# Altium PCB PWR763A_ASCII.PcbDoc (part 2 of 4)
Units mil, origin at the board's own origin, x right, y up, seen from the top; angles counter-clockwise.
Board outline 5000 x 7000 mil, 4 copper layers (Top Layer, Signal Layer 1, Signal Layer 2, Bottom Layer), stack 61.2 mil thick; 559 components, 281 nets, 1477 pads, 685 vias.
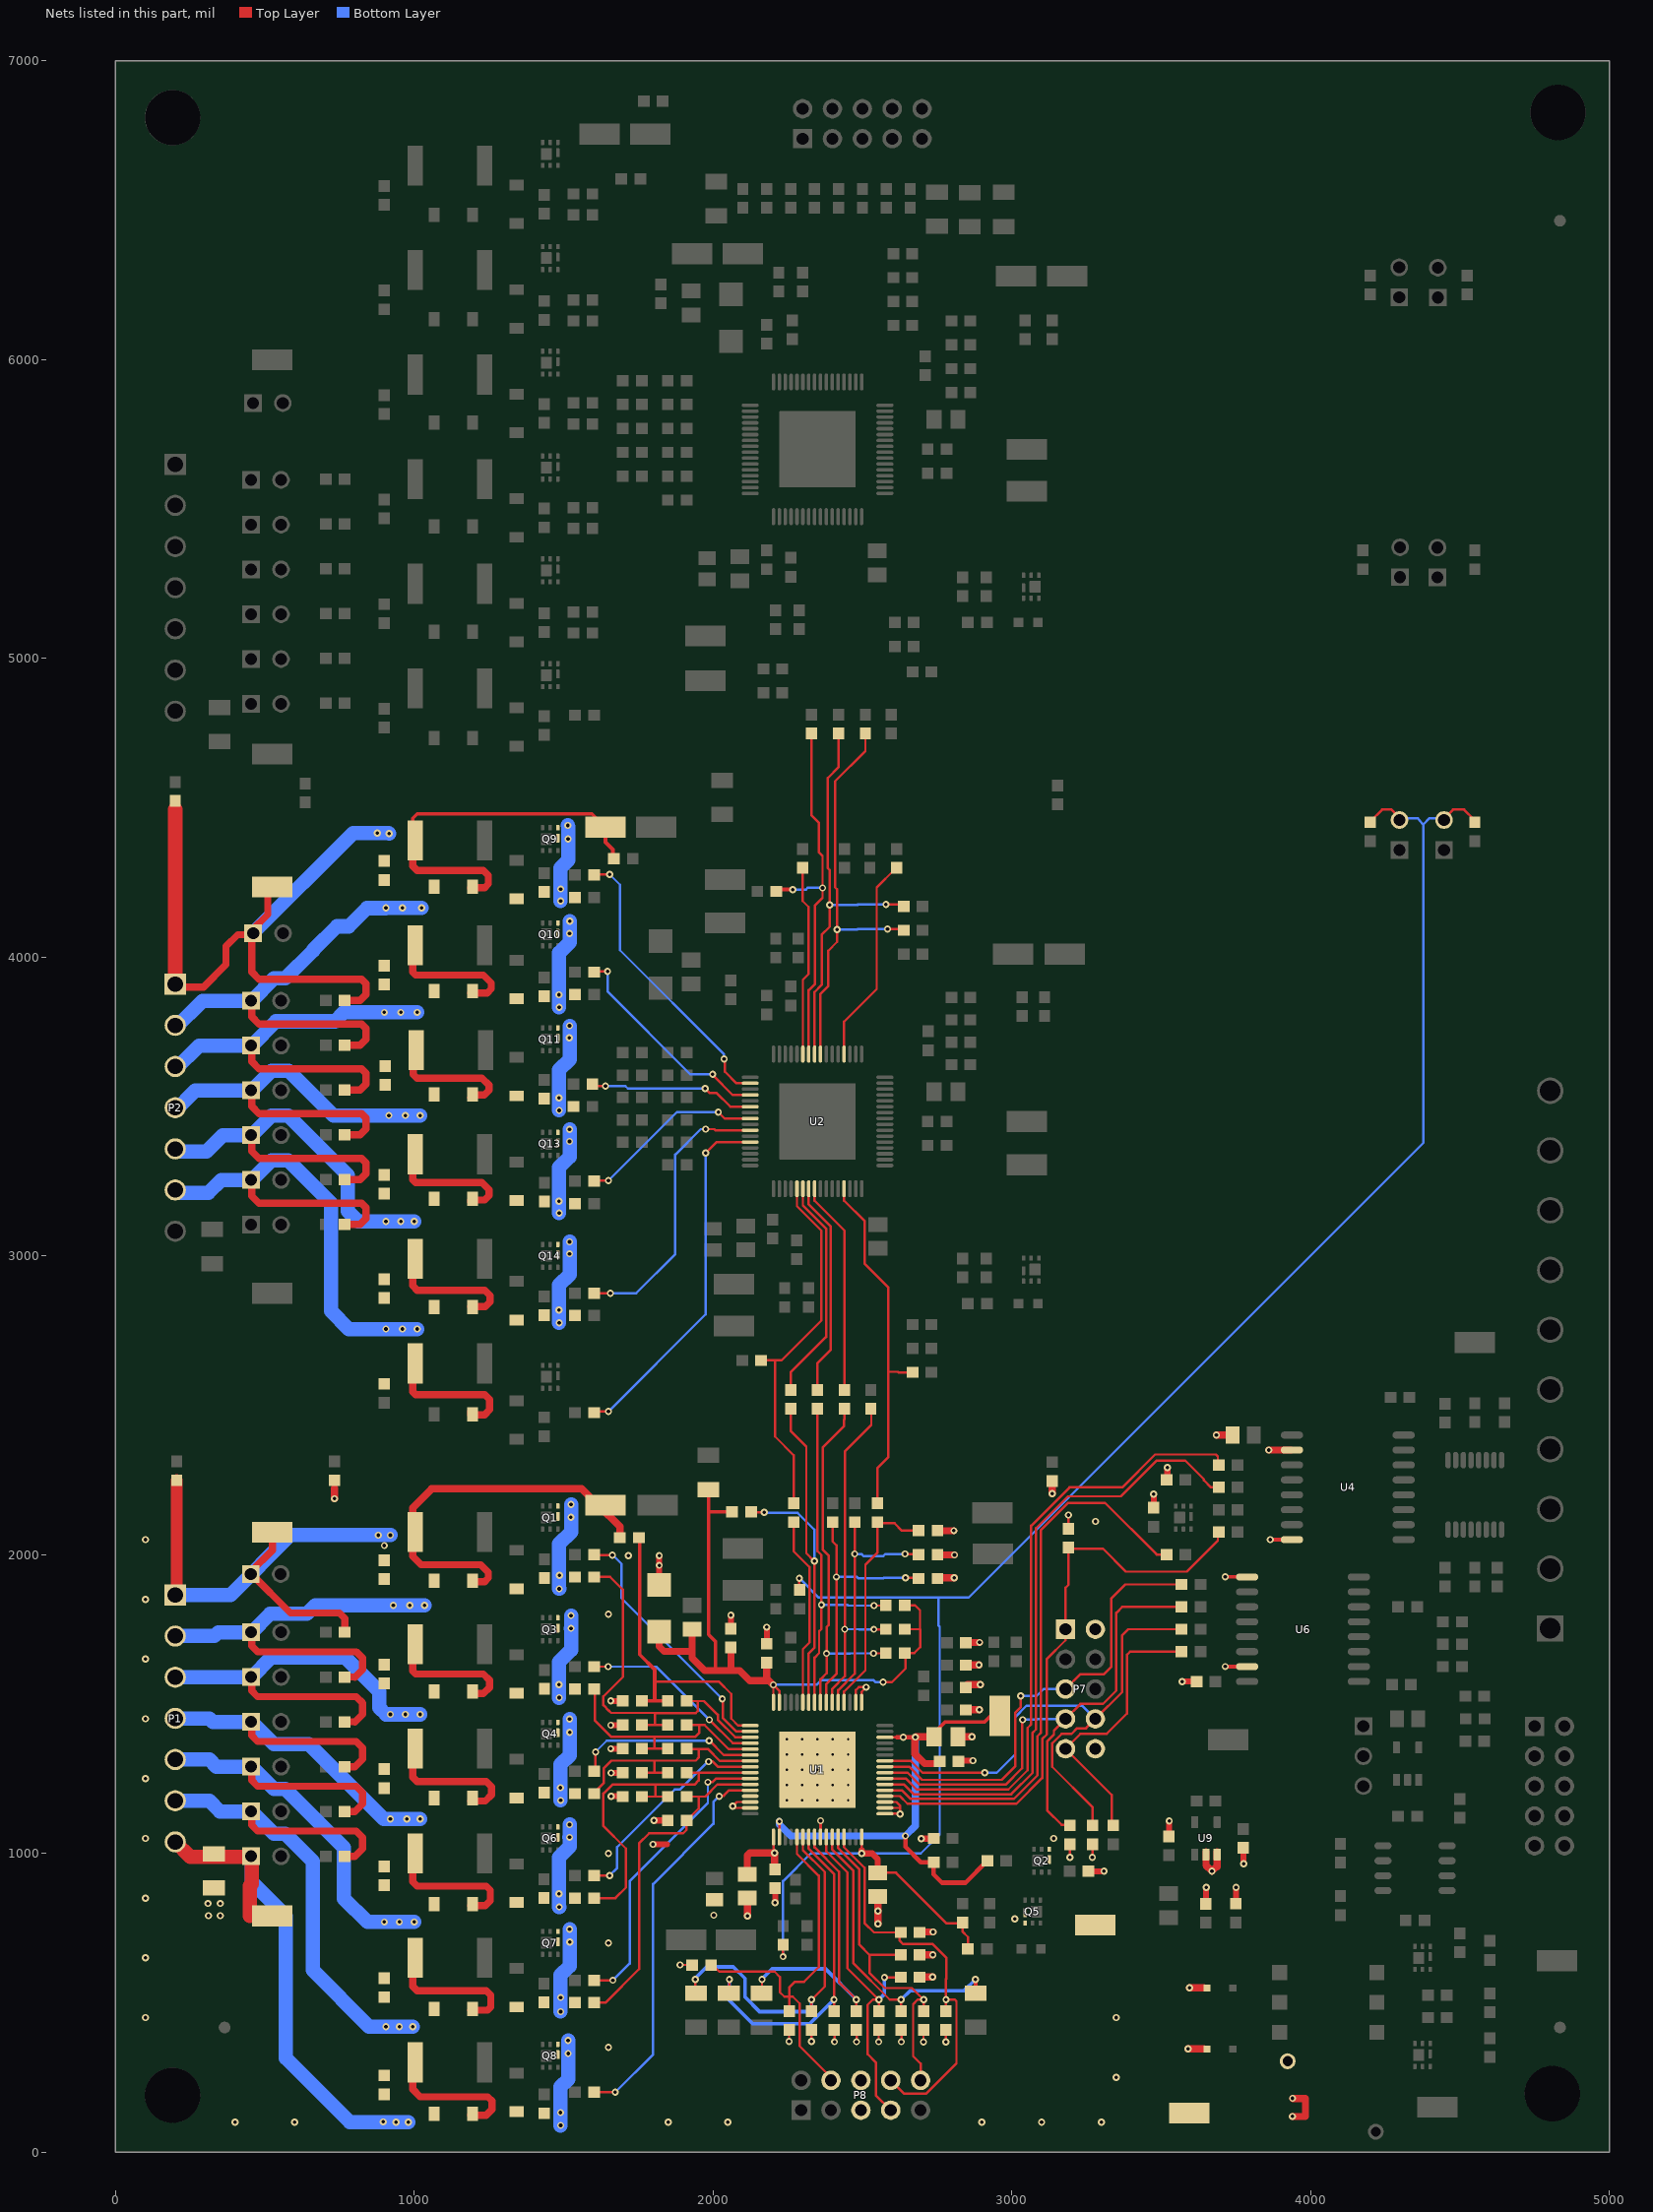
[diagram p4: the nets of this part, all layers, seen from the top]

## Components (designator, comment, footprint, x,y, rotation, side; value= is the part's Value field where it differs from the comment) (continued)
Z5 "MMSZ5232B-7-F" SOD-123 1343,1600 r270 top
Z6 "MMSZ5232B-7-F" SOD-123 1131,1185 r180 top
Z7 "MMSZ5232B-7-F" SOD-123 1343,1250 r270 top
Z8 "MMSZ5232B-7-F" SOD-123 1131,830 r180 top
Z9 "MMSZ5232B-7-F" SOD-123 1343,900 r270 top
Z10 "MMSZ5232B-7-F" SOD-123 1131,479 r180 top
Z11 "MMSZ5232B-7-F" SOD-123 1343,550 r270 top
Z12 "MMSZ5232B-7-F" SOD-123 1131,128 r180 top
Z13 "MMSZ5232B-7-F" SOD-123 1343,200 r270 top
Z14 "MMSZ5232B-7-F" SOD-123 1131,4236 r180 top
Z15 "SMAJ36CA" SMA 1825,3975 r270 top
Z16 "MMSZ5232B-7-F" SOD-123 1343,4260 r270 top
Z17 "MMSZ5232B-7-F" SOD-123 1131,3887 r180 top
Z18 "MMSZ5232B-7-F" SOD-123 1343,3925 r270 top
Z19 "MMSZ5232B-7-F" SOD-123 1131,3540 r180 top
Z20 "MMSZ5232B-7-F" SOD-123 1343,3600 r270 top
Z21 "MMSZ5232B-7-F" SOD-123 1131,3191 r180 top
Z22 "MMSZ5232B-7-F" SOD-123 1343,3250 r270 top
Z23 "MMSZ5232B-7-F" SOD-123 1131,2828 r180 top
Z24 "MMSZ5232B-7-F" SOD-123 1343,2850 r270 top
Z25 "MMSZ5232B-7-F" SOD-123 1131,2470 r180 top
Z26 "MMSZ5232B-7-F" SOD-123 1343,2450 r270 top
Z27 "SMAJ36CA" SMA 2060,6140 r270 top
Z28 "MMSZ5232B-7-F" SOD-123 1131,6485 r180 top
Z29 "MMSZ5232B-7-F" SOD-123 1343,6520 r270 top
Z30 "MMSZ5232B-7-F" SOD-123 1131,6135 r180 top
Z31 "MMSZ5232B-7-F" SOD-123 1343,6170 r270 top
Z32 "MMSZ5232B-7-F" SOD-123 1131,5790 r180 top
Z33 "MMSZ5232B-7-F" SOD-123 1343,5820 r270 top
Z34 "MMSZ5232B-7-F" SOD-123 1131,5442 r180 top
Z35 "MMSZ5232B-7-F" SOD-123 1343,5470 r270 top
Z36 "MMSZ5232B-7-F" SOD-123 1131,5089 r180 top
Z37 "MMSZ5232B-7-F" SOD-123 1343,5120 r270 top
Z38 "MMSZ5232B-7-F" SOD-123 1131,4734 r180 top
Z39 "MMSZ5232B-7-F" SOD-123 1343,4770 r270 top
ZZ1 "This Assembly Note is for PCB labels only" AssemblyNoteLabel 150,7739 r0 top
ZZ2 "These assemblies are ESD sensitive, ESD precautions shall be observed." AssemblyNote 150,7630.11 r0 top
ZZ3 "These assemblies must be clean and free from flux and all contaminants. Use of no clean flux is not acceptable." AssemblyNote 150,7541.56 r0 top
ZZ4 "These assemblies must comply with workmanship standards IPC-A-610 Class 2, unless otherwise specified." AssemblyNote 150,7453 r0 top
ZZ5 "Please place P9- Terminal; P10- Terminal; P11- Terminal; to P1; P2; P3" AssemblyNote 145,7320 r0 top

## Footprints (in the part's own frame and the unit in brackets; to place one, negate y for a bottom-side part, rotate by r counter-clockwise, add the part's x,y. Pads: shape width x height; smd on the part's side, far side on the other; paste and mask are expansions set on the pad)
0603#1 [mm] "0603 from SM-752 data"
  rect 1x0.95 smd: 1(-0.8,0) 2(0.8,0)
  silkscreen extent -1.52,-0.69 1.52,0.69
0603#2 [mm] "0603 from SM-752 data"
  rect 1x0.95 smd: 1(-2.832,4.877) 2(-1.232,4.877)
  silkscreen extent -3.56,4.19 -0.51,5.57
0805_145 [mm] "0805 / 1.45mm height"
  rect 1.15x1.45 smd: 1(-0.9,0) 2(0.9,0)
  silkscreen extent -0.1,-0.8 0.1,0.8
0805_HV [mil] "0805 with 30mil clearance between pads"
  rect 50x63 smd: 1(-40,0) 2(40,0)
  silkscreen extent -74,-40 74,40
1206 [mm] "1206 from SM-752 data"
  rect 1.3x1.85 smd: 1(-1.45,0) 2(1.45,0)
  silkscreen extent -2.4,-1.21 2.4,1.21
2512 [mm] "Chip Resistor, Body 6.3x3.2mm, IPC Medium Density"
  rect 1.3x3.4 smd: 1(-2.95,0) 2(2.95,0)
  silkscreen extent -1.9,-1.6 1.9,1.6
APT1608_Yellow [mm] "SMD, 2-Leads, Body 0.8x1.6mm"
  rect 0.8x0.8 smd: 1(-0.825,0) 2(0.825,0)
  silkscreen extent -1,-0.7 1.8,0.7
AssemblyNote [mil] "Assembly Note"
AssemblyNoteLabel [mil] "Assembly Note for PCB Labels"
CAPRD750W60D700H1000 [mm] "muRata"
  round 1.35 hole 0.85: 1(-3.75,3) 2(3.75,-3)
  silkscreen extent -3.5,-2.95 3.47,3.05
Coilcraft_Q4470-CL [mm] "SMD, 6-Leads, Body 6.6x6.99mm, Pitch 2.54mm"
  rect 1.27x1.27 smd: 1(-4.13,2.54) 2(-4.13,0) 3(-4.13,-2.54) 4(4.13,-2.54) 5(4.13,0) 6(4.13,2.54)
  silkscreen extent -3.4,-3.5 3.3,3.8
CONN_5103308-1 [mm] "TE Connectivity (AMP) Rev E datasheet"
  rect 1.65x1.65 hole 1.016 mask+0: 1(-5.08,-1.27)
  round 1.65 hole 1.016 mask+0: 2(-5.08,1.27) 3(-2.54,-1.27) 4(-2.54,1.27) 5(0,-1.27) 6(0,1.27) 7(2.54,-1.27) 8(2.54,1.27) 9(5.08,-1.27) 10(5.08,1.27)
  silkscreen extent -10.16,-4.57 10.16,4.57
CONN_PEC02SAAN [mm] "SULLINS"
  rect 1.5x1.5 hole 1.016: 1(-1.27,0)
  round 1.5 hole 1.016: 2(1.27,0)
  silkscreen extent -3.45,-1.27 2.54,1.27
CONN_PEC03SAAN [mm] "SULLINS"
  rect 1.5x1.5 hole 1.016: 1(-2.54,0)
  round 1.5 hole 1.016: 2(0,0) 3(2.54,0)
  silkscreen extent -4.72,-1.27 3.81,1.27
D0008A_N [mm] "SOIC, 8-Leads, Body 4.9x3.9mm, Pitch 1.27mm, IPC Medium Density"
  oval 1.45x0.6 smd: 1(-2.725,1.905) 2(-2.725,0.635) 3(-2.725,-0.635) 4(-2.725,-1.905) 5(2.725,-1.905) 6(2.725,-0.635) 7(2.725,0.635) 8(2.725,1.905)
  silkscreen extent -3.3,-2.5 0.9,2.5
DBV0005A_N [mm] "SOT23, 5-Leads, Body 2.9x1.6mm, Pitch 0.95mm, Lead Span 2.8mm, IPC Medium Density"
  rrect17% 1x0.6 smd: 1(-1.375,0.95) 2(-1.375,0) 3(-1.375,-0.95) 4(1.375,-0.95) 5(1.375,0.95)
  silkscreen extent -1.63,-1.55 0.38,1.55
DW0016A_N [mm] "SOIC, 16-Leads, Body 10.3x7.5mm, Pitch 1.27mm, IPC Medium Density"
  oval 1.9x0.6 smd: 1(-4.75,4.445) 2(-4.75,3.175) 3(-4.75,1.905) 4(-4.75,0.635) 5(-4.75,-0.635) 6(-4.75,-1.905) 7(-4.75,-3.175) 8(-4.75,-4.445) 9(4.75,-4.445) 10(4.75,-3.175) 11(4.75,-1.905) 12(4.75,-0.635) 13(4.75,0.635) 14(4.75,1.905) 15(4.75,3.175) 16(4.75,4.445)
  silkscreen extent -5.6,-5.25 3,5.25
FCC_disclaimer [mil]
Fiducial10-20#1 [mm]
  round 1 smd mask+0.5: 1(0,0)
  Top Layer keep-out circle w1.178: c0,0 r0.5
Fiducial10-20#2 [mm]
  round 1 smd mask+0.5: 1(0,-0.076)
  Top Layer keep-out circle w1.178: c0,0 r0.5
Fiducial10-20#3 [mm]
  round 1 smd mask+0.5: 1(0.102,0)
  Top Layer keep-out circle w1.178: c0,0 r0.5
IEC_HighVoltage_Small [mil]
  silkscreen extent -107,-88 107,97
Keystone_9030 [mm] "BRD SPT SNAP LOCK SCREW MNT 3/8\""
  round 4.7 hole 4.7 unplated mask+0: ""(0,0)
  silkscreen extent -3.3,-3.3 3.3,3.3
Label_650x200 [mil] "Thermal Transfer Label"
  round 1 on Mech13: 0(0,0)
  silkscreen extent -325,-100 325,100
Molex_395021007 [mm] "Header(Shrouded), 3.5mm, 7x1,  R/A, TH"
  rect 1.8x1.8 hole 1.3: 1(-10.5,0)
  round 1.8 hole 1.3: 2(-7,0) 3(-3.5,0) 4(0,0) 5(3.5,0) 6(7,0) 7(10.5,0)
  silkscreen extent -12.95,-7.87 12.95,1.52
PAP0064F_N [mm] "Thin QFP, 64-Leads, Body 10x10mm, Pitch 0.5mm, Thermal Pad 6.5x6.5mm, IPC Medium Density"
  rrect100% 1.45x0.3 smd: 1(-5.725,3.75) 2(-5.725,3.25) 3(-5.725,2.75) 4(-5.725,2.25) 5(-5.725,1.75) 6(-5.725,1.25) 7(-5.725,0.75) 8(-5.725,0.25) 9(-5.725,-0.25) 10(-5.725,-0.75) 11(-5.725,-1.25) 12(-5.725,-1.75) 13(-5.725,-2.25) 14(-5.725,-2.75) 15(-5.725,-3.25) 16(-5.725,-3.75) 33(5.725,-3.75) 34(5.725,-3.25) 35(5.725,-2.75) 36(5.725,-2.25) 37(5.725,-1.75) 38(5.725,-1.25) 39(5.725,-0.75) 40(5.725,-0.25) 41(5.725,0.25) 42(5.725,0.75) 43(5.725,1.25) 44(5.725,1.75) 45(5.725,2.25) 46(5.725,2.75) 47(5.725,3.25) 48(5.725,3.75)
  rrect100% 0.3x1.45 smd: 17(-3.75,-5.725) 18(-3.25,-5.725) 19(-2.75,-5.725) 20(-2.25,-5.725) 21(-1.75,-5.725) 22(-1.25,-5.725) 23(-0.75,-5.725) 24(-0.25,-5.725) 25(0.25,-5.725) 26(0.75,-5.725) 27(1.25,-5.725) 28(1.75,-5.725) 29(2.25,-5.725) 30(2.75,-5.725) 31(3.25,-5.725) 32(3.75,-5.725) 49(3.75,5.725) 50(3.25,5.725) 51(2.75,5.725) 52(2.25,5.725) 53(1.75,5.725) 54(1.25,5.725) 55(0.75,5.725) 56(0.25,5.725) 57(-0.25,5.725) 58(-0.75,5.725) 59(-1.25,5.725) 60(-1.75,5.725) 61(-2.25,5.725) 62(-2.75,5.725) 63(-3.25,5.725) 64(-3.75,5.725)
  rrect2% 6.5x6.5 smd: 65(0,0)
  silkscreen extent -5.67,-4.25 4.25,4.57
Pb-Free_Overlay_Small [mil]
  silkscreen extent -46,-46 46,46
PW0016A_N [mm] "TSOP, 16-Leads, Body 5x4.4mm, Pitch 0.65mm, IPC Medium Density"
  oval 1.4x0.45 smd: 1(-2.95,2.275) 2(-2.95,1.625) 3(-2.95,0.975) 4(-2.95,0.325) 5(-2.95,-0.325) 6(-2.95,-0.975) 7(-2.95,-1.625) 8(-2.95,-2.275) 9(2.95,-2.275) 10(2.95,-1.625) 11(2.95,-0.975) 12(2.95,-0.325) 13(2.95,0.325) 14(2.95,0.975) 15(2.95,1.625) 16(2.95,2.275)
  silkscreen extent -3.5,-2.55 1.85,2.75
Samtec_HPM-10-05-T-S [mm] "Header, 5.08mm, 10x1, TH"
  rect 2.25x2.25 hole 1.75: 1(-22.86,0)
  round 2.25 hole 1.75: 2(-17.78,0) 3(-12.7,0) 4(-7.62,0) 5(-2.54,0) 6(2.54,0) 7(7.62,0) 8(12.7,0) 9(17.78,0) 10(22.86,0)
  silkscreen extent -25.47,-3.17 25.33,3.8
SMA [mm] "Molded Diode, 2-Leads, Body 4.3x2.6mm, IPC Medium Density, based on OnSemi component dimensions and land pattern"
  rect 2x2 smd: 1(-2,0) 2(2,0)
  silkscreen extent -3.66,-1.57 2.79,1.57
SNT-100-BK-G [mil] "Samtec STEP model"
  round 1 on Mech3: 0(0,0)
SOD-123 [mm] "On Semi recommended land pattern"
  rect 0.915x1.22 smd: 1(-1.637,0) 2(1.637,0)
  silkscreen extent -2.74,-1.17 2.03,1.17
sod-323 [mm] "NXP recommended land pattern"
  rect 0.6x0.6 smd paste-0.05: 1(-1.1,0) 2(1.1,0)
  silkscreen extent -1.8,-0.77 1.53,0.77
Testpoint_Keystone_Miniature [mil] "Miniature SMT test point"
  rect 135x70 smd: 1(0,0)
  silkscreen extent -78,-46 78,45
TI_Stacked_Overlay_Small [mil]
TRANS_NexFET_Q2 [mm] "TI recommended land pattern M0167-01"
  rrect33% 0.45x0.3 smd: 1(-0.975,0.65) 2(-0.975,0) 3(-0.975,-0.65) 4(0.975,-0.65) 5(0.975,0) 6(0.975,0.65)
  rrect33% 0.75x0.3 smd paste-0.025: 7(0.095,-0.65)
  rrect11% 1x0.95 smd paste-0.025: 8(0,0.325)
  silkscreen extent -1.15,-1.15 1.15,1.15

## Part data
C1 C2 C3 C4 C5 C10 C11 C12 C13 C14 C17 C18 C20 C21 C25 C26 C28 C29 C40 C41 C42 C44 C46 C48 C51 C52 C54 C55 C57 C60 C66 C67 C78 C79 C80 C82 C84 C86 C89 C90 C92 C93 C95 C98 C100 C101 C107 C113 C114 C116 C118 C120 C121 C122 C123 C124 C125 C129 C132 C133: "CAP, CERM, 0.1 µF, 50 V, +/- 10%, X7R, 0603"
C6 C7 C8 C9: "CAP, CERM, 3300 pF, 50 V, +/- 10%, X7R, 0603"
C15 C16 C19 C24 C27 C30 C34 C49 C50 C53 C56 C61 C68 C69 C87 C88 C91 C94 C99 C102 C103: "CAP, CERM, 0.1 µF, 100 V, +/- 10%, X7R, 0603"
C22 C23 C58 C59 C96 C97: "CAP, CERM, 0.047 µF, 16 V, +/- 10%, X7R, 0603"
C31 C32 C33 C70 C71 C72 C104 C105 C106: "CAP, CERM, 0.1 µF, 16 V, +/- 10%, X7R, 0603"
C35 C36 C37 C38 C62 C63 C64 C65 C73 C74 C75 C76 C108 C109 C110 C111: "CAP, CERM, 33 pF, 50 V, +/- 5%, C0G/NP0, 0603"
C39 C77 C112 C126 C135: "CAP, CERM, 10 µF, 10 V, +/- 20%, X7R, 0805"
C43 C45 C47 C81 C83 C85 C115 C117 C119: "CAP, CERM, 2.2 µF, 10 V, +/- 10%, X7R, 0805"
C127: "CAP, CERM, 1 µF, 16 V, +/- 10%, X7R, 0603"
C128 C130 C131 C134: "CAP, CERM, 4.7 µF, 10 V, +/- 10%, X5R, 0603"
C136: "CAP, CERM, 150 pF, 50 V, +/- 5%, C0G/NP0, 0603"
C137: "CAP, CERM, 1000 pF, 3150 V, +80/-20%, E, Radial Disc D7x6mm"
"CAUTION 1": library part IEC_HighVoltage, "IEC 61010-1 High Voltage Warning"
D1 D2 D3: "LED, Yellow, SMD"
D4: "MOSFET, P-CH, -20 V, -20 A, SON 2x2mm"
D5 D6: "Diode, Schottky, 30 V, 0.2 A, SOD-323"
FID1 FID2 FID3: "Fiducial mark.  There is nothing to buy or mount."
H1 H2 H3 H4: "BRD SPT SNAP LOCK SCREW MNT 3/8\""
J1 J2 J3 J4 J5 J6 J7 J8 J9 JP1 JP2 JP3 JP4 JP5 JP6 JP7 JP8 JP9 JP10 JP11 JP12 JP13 JP14 JP15 JP16 JP17 JP18: "Header, 100mil, 2x1, Tin, TH"
JP19: "Header, 100mil, 3x1, Tin, TH"
L1: "Inductor, Wirewound, Ferrite, 10uH, 0.12A, 0.5 ohm, SMD"
LBL1: library part THT-14-423-10, "Thermal Transfer Printable Labels, 0.650\" W x 0.200\" H - 10,000 per roll"
Logo1: library part TI_Logo, "Texas Instrument Corporate Signature"
Logo2: library part Pb-Free
Logo3: library part FCC_disclaimer, "FCC_disclaimer"
P1 P2 P3: "Header(Shrouded), 3.5mm, 7x1,  R/A, TH"
P4 P5 P7 P8: "Header (shrouded), 100mil, 5x2, Gold, TH"
P6: "Header, 5.08mm, 10x1, Tin, TH"
Q1 Q2 Q3 Q4 Q5 Q6 Q7 Q8 Q9 Q10 Q11 Q12 Q13 Q14 Q15 Q16 Q17 Q18 Q19 Q20 Q21 Q22 Q23 Q24: "MOSFET, N-CH, 25 V, 5 A, SON 2x2mm"
R1 R10 R11 R12 R54 R55 R56 R65: "RES, 1.00 k, 1%, 0.25 W, 1206"
R2 R3 R4 R5 R6 R7 R8 R9 R20 R37 R57 R58 R59 R60 R61 R62 R63 R64 R94 R96 R99 R101 R103 R104 R105 R106 R108 R140 R141 R144 R146 R177 R179 R181 R184 R185 R198 R199 R200: "RES, 0, 5%, 0.1 W, 0603"
R13 R14 R15 R16 R17 R18 R30 R31 R32 R33 R34 R35 R47 R48 R49 R50 R51 R52: "RES, 1.0 k, 5%, 0.1 W, 0603"
R19 R29 R36 R46 R53: "RES, 0, 5%, 0.25 W, 1206"
R21 R22 R23 R24 R25 R26 R27 R28 R38 R39 R40 R41 R42 R43 R44 R45 R67 R69 R72 R73 R76 R79 R87 R92 R95 R98 R102 R109 R111 R114 R116 R118 R120 R122 R125 R131 R136 R138 R142 R145 R148 R151 R153 R155 R157 R159 R162 R164 R173 R175 R178 R182 R186 R202 R214: "RES, 1.00 k, 0.1%, 0.1 W, 0603"
R66 R74 R81 R93 R100 R110 R113 R119 R124 R133 R139 R147 R150 R156 R160 R167 R176 R183: "RES, 47, 5%, 1 W, 2512"
R68 R115 R152: "RES, 0, 5%, 0.125 W, 0805"
R70 R75 R80 R82 R83 R196 R207 R208 R209 R211: "RES, 10.0 k, 1%, 0.1 W, 0603"
R71 R78 R90 R97 R107 R112 R117 R121 R129 R137 R143 R149 R154 R158 R163 R174 R180 R187 R190 R191 R192 R195: "RES, 1.0 M, 5%, 0.1 W, 0603"
R77 R123 R161: "RES, 1.6 k, 5%, 0.1 W, 0603"
R84 R85 R127 R128 R165 R166: "RES, 1.47 k, 1%, 0.1 W, 0603"
R86 R126 R135 R168 R172 R204: "RES, 100 k, 1%, 0.1 W, 0603"
R88 R130 R171 R188 R189 R193 R194 R197 R201 R203 R205 R206: "RES, 100, 5%, 0.1 W, 0603"
R89 R91 R132 R134 R169 R170: "RES, 1.82 k, 1%, 0.1 W, 0603"
R210: "RES, 2.00, 1%, 0.1 W, 0603"
R212: "RES, 523 k, 1%, 0.1 W, 0603"
R213: "RES, 169 k, 1%, 0.1 W, 0603"
R215: "RES, 1.0, 5%, 0.1 W, 0603"
RT1 RT2 RT3 RT4 RT5 RT6: "Thermistor NTC, 10.0k ohm, 1%, 0603"
SH-J1 SH-J2 SH-J3 SH-J4 SH-J5 SH-J6 SH-J7 SH-J8 SH-JP1 SH-JP2 SH-JP3 SH-JP4 SH-JP5 SH-JP6 SH-JP7 SH-JP8 SH-JP9 SH-JP10 SH-JP11 SH-JP12 SH-JP13 SH-JP14 SH-JP15 SH-JP16 SH-JP17 SH-JP18 SH-JP19: "Shunt, 100mil, Gold plated, Black"
T1: "Transformer, 400 uH, SMT"
TP1 TP2 TP3 TP4 TP5 TP6 TP-1 TP-2 TP-3 TP-4 TP-5 TP-6 TP-7 TP-8 TP-9 TP-10 TP-11 TP-12 TP-13 TP-14 TP-15 TP-16 TP-17 TP-18 TP-19 TP-AGN TP-C1 TP-C2 TP-C3 TP-C4 TP-C5 TP-C6 TP-SW1 TP-VPROG1 TP-VPROG2 TP-VPROG3 TP-VSS1 TP-VSS2 TP-VSS3 TPTP-VSS1: "Test Point, Miniature, SMT"
TP-20: "LOW PROFILE, TH"
U1 U2 U3: "Lithium-Ion Battery Monitor and Secondary Protection IC for Electric and Hybrid, -40 to 85 degC, 64-pin HTQFP (PAP), Green (RoHS & no Sb/Br)"
U4 U6: "25 Mbps Quad Channels, 3 / 1, Digital Isolator, 3.3 V / 5 V, -40 to +125 degC, 16-pin SOIC (DW), Green (RoHS & no Sb/Br)"
U5: "Remote 8-Bit I2C and SMBus Low-Power I/O Expander with Reset and Configuration Registers, 2.3 to 5.5 V, -40 to 85 degC, 16-pin TSSOP (PW), Green (RoHS & no Sb/Br)"
U7: "Single Output LDO, 100 mA, Fixed 3.3 V Output, 2.7 to 10 V Input, with Low IQ, 5-pin SOT-23 (DBV), -40 to 125 degC, Green (RoHS & no Sb/Br)"
U8: "LOW POWER CURRENT MODE PUSH-PULL PWM, D0008A"
U9: "Ultralow-Power 100-mA Low-Dropout Linear Regulators, DBV0005A"
Z1 Z15 Z27: "Diode, TVS, Bi, 36 V, 400 W, SMA"
Z2 Z3 Z4 Z5 Z6 Z7 Z8 Z9 Z10 Z11 Z12 Z13 Z14 Z16 Z17 Z18 Z19 Z20 Z21 Z22 Z23 Z24 Z25 Z26 Z28 Z29 Z30 Z31 Z32 Z33 Z34 Z35 Z36 Z37 Z38 Z39: "Diode, Zener, 5.6 V, 500 mW, SOD-123"
ZZ1: library part AssemblyNoteLabel
ZZ2 ZZ3 ZZ4 ZZ5: library part AssemblyNote

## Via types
v1: diameter 24, hole 12, Top Layer to Bottom Layer, tented both sides, 607 vias
v2: diameter 19.68, hole 7.87, Top Layer to Bottom Layer, 75 vias
v3: diameter 22, hole 10, Top Layer to Bottom Layer, tented both sides, 3 vias

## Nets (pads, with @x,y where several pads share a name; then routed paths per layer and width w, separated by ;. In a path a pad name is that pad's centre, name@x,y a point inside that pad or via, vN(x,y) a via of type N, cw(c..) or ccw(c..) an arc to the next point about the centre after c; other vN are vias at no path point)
1-ALERT: R189.1 U1.38 | length 2099.8
  Top Layer w8: U1.38@2578.35,1230.79 2638.9,1230.79 2671.68,1198 2998,1198 3069.97,1269.97 3069.97,1403.6 3081.1,1414.73 3081.1,2088.02 3188.08,2195 3365,2195 3485,2315 3580.36,2315 3642.76,2252.6 3642.76,2249.24 3667,2225 R189.1@3690,2225
1-ALERT_N: C37.1 R39.1 U1.57 | length 1205.3
  Top Layer w8: U1.57@2340.16,1508.35 2340.16,1655.08 2355.13,1670.05 2355.13,1743.04 2363.13,1751.04 v1(2363.13,1832.04) 2363.13,1998.23 2350,2011.36 R39.1@2350,2485 ; v1(2538.91,1829.32) 2575,1829.32 C37.1@2575,1830
  Bottom Layer w8: v1(2363.13,1832.04) 2449.66,1832.04 2452.38,1829.32 v1(2538.91,1829.32)
1-ALERT_S: R55.2 R59.2 U1.23 | length 1144.9
  Top Layer w8: R55.2@2053,531.57 2055,533.57 v1(2055,578) ; U1.23@2320.47,1051.65 2320.47,1015.22 2405,930.69 v1(2405,510) R59.2@2405,475
  Bottom Layer w12: v1(2055,578) 2055,507 2132,430 2325,430 v1(2405,510)
1-CB1: R111.1 U1.12 | length 1316.4
  Top Layer w8: R111.1@1601.5,200 1601.72,200.22 v1(1672.75,200.22) ; v1@2022,1193 2036,1193 2054.1,1211.1 U1.12@2124.61,1211.1
  Bottom Layer w8: v1(1672.75,200.22) 1799.55,327.01 1799.55,897.05 2001.53,1099.03 2001.53,1171.96 v1@2020.61,1191.04
  other v1: 2020.96,1190.97
1-CB2: R102.1 U1.10 | length 1009
  Top Layer w8: R102.1@1601.5,575 v1@1664.93,575 ; v1@1979,1238 1998,1238 2010.47,1250.47 U1.10@2124.61,1250.47
  Bottom Layer w8: v1@1664.9,575 1721,631.1 1721,906.02 1982.96,1167.98 v1(1982.96,1237.97)
  other v1: 1664.96,574.97
1-CB3: R95.1 U1.8 | length 725
  Top Layer w8: R95.1@1601.5,925 1602.33,925.83 v1(1654.07,925.83) ; v1@1987,1308 1998,1308 2016.16,1289.84 U1.8@2124.61,1289.84
  Bottom Layer w8: v1(1654.07,925.83) 1679.49,951.25 1679.49,1020.91 1871.81,1213.24 1889.08,1213.24 v1@1982.46,1306.62
  other v1: 1984.96,1306.97
1-CB4: R87.1 U1.6 | length 618.8
  Top Layer w8: R87.1@1601.5,1275 1606.96,1280.46 v1(1606.96,1338.97) ; v1@1988,1377.31 2036.1,1329.21 U1.6@2124.61,1329.21
  Bottom Layer w8: v1@1606.55,1339.16 1644.36,1376.97 v1(1986.96,1376.97)
1-CB5: R76.1 U1.4 | length 628.8
  Top Layer w8: R76.1@1601.5,1625 v1@1648.93,1625 ; v1(1987.96,1446.97) 2066.42,1368.58 U1.4@2124.61,1368.58
  Bottom Layer w8: v1@1649.41,1624.83 1810.1,1624.83 v1(1987.96,1446.97)
  other v1: 1648.96,1624.97
1-CB6: R69.1 U1.2 | length 868.8
  Top Layer w8: R69.1@1601.5,2000 1603.53,1997.97 v1(1662.96,1997.97) ; v1@2032.65,1515.22 2032.65,1453.35 2078.05,1407.95 U1.2@2124.61,1407.95
  Bottom Layer w8: v1@1663.97,1998.87 1693.86,1968.98 1693.86,1854.07 v1(2030.96,1516.97)
1-CELL1: C34.2 C42.1 JP17.1 P1.6 Q7.4 Q7.7 R52.2 R107.1 R109.2 R110.2 Z10.2 Z11.2 Z12.1 | length 2632.2
  Top Layer w24: JP17.1@456,1140 456,1094 475.34,1074.66 805.63,1074.66 826.99,1053.3 826.99,1014.97 801.51,989.49 801,990 R52.2@770,990 ; R110.2@995,300 995,210 1020,185 1246.45,185 1259.94,171.51 1259.94,142.51 1240.14,122.71 1189.5,122.71 Z12.1@1189.5,125
  Bottom Layer w48: P1.6@200,1176.02 313.89,1176.02 349.91,1140 456,1140 531,1065 568.68,1065 660,973.68 660,608.43 848.43,420 v1(905,420) v1(950,420) v1(995,420) ; v1(1490,470) 1490,593 1520,623 1520,702.84 v1(1520.82,702.84) 1520,706 v1(1520,746)
  other v1: 1490.24,517.34
1-CELL2: C28.2 C34.1 JP16.1 P1.5 Q6.4 Q6.7 R51.2 R97.1 R98.2 R100.2 Z8.2 Z9.2 Z10.1 | length 2434.2
  Top Layer w24: JP16.1@456,1290 456,1244 475.34,1224.66 805.63,1224.66 826.99,1203.3 826.99,1164.97 801.51,1139.49 801,1140 R51.2@770,1140 ; R100.2@995,650 995,555 1010,540 1241.45,540 1256.21,525.24 1256.21,485.78 1245.43,475 Z10.1@1189.5,475
  Bottom Layer w48: P1.5@200,1313.81 313.89,1313.82 337.71,1290 456,1290 531,1215 568.68,1215 765,1018.68 765,848.43 843.43,770 v1(900,770) v1(950,770) v1(1000,770) ; v1(1485.15,820.54) 1485,824 1485,987 1520,1022 1520,1053.48 v1(1519.89,1053.48) 1520,1056 v1(1520,1096)
  other v1: 1484,864
1-CELL3: C25.2 C28.1 JP15.1 P1.4 Q4.4 Q4.7 R50.2 R90.1 R92.2 R93.2 Z6.2 Z7.2 Z8.1 | length 2257.2
  Top Layer w24: JP15.1@456,1440 456,1394 475.34,1374.66 805.63,1374.66 826.99,1353.3 826.99,1314.97 801.51,1289.49 801,1290 R50.2@770,1290 ; R93.2@995,1000 995,905 1010,890 1241.45,890 1254.55,876.9 1254.55,841.55 1238,825 Z8.1@1189.5,825
  Bottom Layer w48: P1.4@200,1451.61 313.89,1451.61 325.5,1440 456,1440 531,1365 647.44,1365 897.44,1115 v1(920,1115) v1(975,1115) v1(1020,1115) ; v1(1490,1177) 1490,1298 1520,1328 v1(1520,1449)
  other v1: 1489.5,1219.45 1520.15,1405.14
1-CELL4: C20.2 C25.1 JP14.1 P1.3 Q3.4 Q3.7 R49.2 R78.1 R79.2 R81.2 Z4.2 Z5.2 Z6.1 | length 2266.3
  Top Layer w24: JP14.1@456,1590 456,1544 475.34,1524.66 805.63,1524.66 826.99,1503.3 826.99,1464.97 801.51,1439.49 801,1440 R49.2@770,1440 ; R81.2@995,1350 995,1255 1010,1240 1241.45,1240 1258.28,1223.17 1258.28,1195.28 1238,1175 Z6.1@1189.5,1175
  Bottom Layer w48: P1.3@200,1589.41 331.6,1589.41 332.19,1590 456,1590 521,1655 770,1655 883,1542 883,1487.19 905.19,1465 v1(920,1465) v1(970,1465) v1(1020,1465) ; v1(1485,1521) 1485,1641 1525,1681 1525,1753.17 v1(1524.74,1753.17) 1525,1756 v1(1525,1796)
  other v1: 1484.41,1564.58
1-CELL5: C17.2 C20.1 JP13.1 P1.2 Q1.4 Q1.7 R48.2 R71.1 R72.2 R74.2 Z2.2 Z3.2 Z4.1 | length 2161.2
  Top Layer w24: JP13.1@456,1740 456,1694 475.34,1674.66 805.63,1674.66 826.99,1653.3 826.99,1614.97 801.51,1589.49 801,1590 R48.2@770,1590 ; R74.2@995,1700 995,1610 1005,1600 1231.45,1600 1251.65,1579.8 1251.65,1555.16 1231.35,1534.86 Z4.1@1199.36,1534.86
  Bottom Layer w48: P1.2@200,1727.2 331.6,1727.2 344.4,1740 456,1740 518,1802 640.34,1802 668.34,1830 v1(930,1830) v1(985,1830) v1(1035,1830) ; v1(1485.26,1885.34) 1485,1890 1485,2036 1525,2076 v1(1525,2168)
  other v1: 1486,1931 1524.45,2124.9
1-CELL6: C17.1 J1.1 P1.1 R37.1 R47.2 R66.2 R67.2 TP5.1 TP-C1.1 Z2.1 | length 3101.4
  Top Layer w24: J1.1@453,1935 453,1943 525,2015 TP5.1@525,2075 ; J1.1@455,1935 585.48,1804.52 750,1804.52 768.09,1786.43 768.09,1740 R47.2@770,1740 ; R66.2@995,2075 995,1994 1022.75,1966.25 1222.57,1966.25 1248.03,1940.78 1248.03,1921.31 1236.02,1909.3 Z2.1@1198.8,1909.3
  Top Layer w25: R66.2@995,2075 995,2156.5 1058.5,2220 1560,2220 1615,2165 1617,2165 1688.52,2093.48 R67.2@1688.52,2056.75
  Top Layer w40: P1.1@200,1865 205,1870 R37.1@205,2248.5
  Bottom Layer w48: P1.1@200,1865 385,1865 585,2065 v1(880,2065) v1(920,2065)
  other v1: 900,2030
1-CONV: P7.1 R83.1 R194.1 U1.36 | length 1977.4
  Top Layer w8: U1.36@2578.35,1191.42 2625.37,1191.42 2650.79,1166 3016,1166 3101.97,1251.97 3101.97,1382.55 3117.77,1398.35 3117.77,1650.7 3180,1712.93 P7.1@3180,1750 3180,1888.75 3190,1898.75 3190,2020 3305,2020 3382.18,1942.82 3585.82,1942.82 3690,2047 R194.1@3690,2075
1-CONV_N: R42.1 U1.59 | length 627.8
  Top Layer w8: R42.1@2270,2105 2270,2011.16 2323,1958.16 2323,1705.62 2300.79,1683.41 U1.59@2300.79,1508.35
1-CONV_S: C10.1 P8.4 R57.2 U1.21 | length 1345.7
  Top Layer w8: C10.1@1993.5,626 1999,626 2021,604 2206,604 2224,586 2224,535 2239,520 2255,520 ; R57.2@2255,475 2255,520 ; U1.21@2281.1,1051.65 2281.1,997.99 2354,925.1 2354,619 2305,570 2275,570 2255,550 2255,520 ; P8.4@2395,240 2395,250 2290,355 2290,497 2267,520 2255,520
1-CS_N: R45.1 R105.2 U1.52 | length 788.2
  Top Layer w8: U1.52@2438.58,1508.35 2438.58,1541 2510.12,1612.54 2510.12,1966.02 2550,2005.91 2550,2105 2607.5,2105 2632.5,2080 R105.2@2685,2080
1-CS_S: C13.1 P8.8 R64.2 U1.29 | length 1353.1
  Top Layer w8: U1.29@2438.58,1051.65 2438.58,1020.36 2507,951.94 2507,767 2539,735 2625,735 2625,707 2636.31,695.69 2735.74,695.69 2780.58,650.85 2780.58,580 2780,579.42 v1(2780,510) ; P8.8@2595,240 2640,195 2712.93,195 2815,297.07 2815,505 2810,510 v1(2780,510) ; R64.2@2780,475 v1(2780,510)
1-DRDY: R196.1 U1.37 | length 1905.2
  Top Layer w8: U1.37@2578.35,1211.1 2632.42,1211.1 2661.53,1182 3007,1182 3085.97,1260.97 3085.97,1391.82 3097.1,1402.95 3097.1,2081.43 3189.02,2173.35 3311.66,2173.35 3485.01,2000 R196.1@3515,2000
1-DRDY_N: C38.1 R38.1 U1.58 | length 1357.3
  Top Layer w8: C38.1@2130.67,2142.55 2130.67,2141.06 v1(2171.82,2141.06) ; R38.1@2260,2485 2260,2413.7 2312.5,2361.21 2312.5,2004.66 v1(2339.13,1978.02) 2339.13,1687.91 2320.47,1669.24 U1.58@2320.47,1508.35
  Bottom Layer w8: v1(2171.82,2141.06) 2171.82,2139.7 2283,2139.7 2339.13,2083.57 v1(2339.13,1978.02)
1-DRDY_S: R54.2 R58.2 U1.22 | length 1208.7
  Top Layer w8: v1(1941,578) 1941,534.57 R54.2@1943,532.57 ; U1.22@2300.79,1051.65 2300.79,1010.44 2374,937.23 2374,554 v1(2330,510) R58.2@2330,475
  Bottom Layer w12: v1(1941,578) 1941,582 1979,620 2068,620 2107,581 2107,519 2156,470 2313,470 2330,487 v1(2330,510)
1-FAULT: R188.1 U1.39 | length 2094.3
  Top Layer w8: U1.39@2578.35,1250.47 2644.95,1250.47 2681.42,1214 2989,1214 3053.2,1278.2 3053.2,1419.71 3065.1,1431.61 3065.1,2096.38 3193.72,2225 3370,2225 3480,2335 3683,2335 3690,2328 R188.1@3690,2300
1-FAULT_N: C36.1 R40.1 U1.56 | length 1221.4
  Top Layer w8: U1.56@2359.84,1508.35 2359.84,1582.4 2380.13,1602.68 v1(2380.13,1669.05) 2380.13,1757.04 2387.13,1764.04 2387.13,1996.86 2368,2015.99 2368,2359.86 2439.12,2430.98 2439.12,2452.05 2440,2452.93 R40.1@2440,2485 ; v1(2537.09,1669.32) 2575,1669.32 C36.1@2575,1670
  Bottom Layer w8: v1(2380.13,1669.05) 2458.48,1669.05 2458.75,1669.32 v1(2537.09,1669.32)
1-FAULT_S: R56.2 R60.2 U1.24 | length 1055.2
  Top Layer w8: R56.2@2163,531.57 2164,532.57 v1(2164,578) ; U1.24@2340.16,1051.65 2340.16,1020 2421.61,938.55 2421.61,568.39 v1(2480,510) R60.2@2480,475
  Bottom Layer w12: v1(2164,578) 2164,579 2198,613 2377,613 v1(2480,510)
1-LDOA: C44.1 C45.1 U1.17 | length 259.3
  Top Layer w8: v1@2202.36,1001.21 U1.17@2202.36,1051.65
  Top Layer w24: C45.1@2115,930 2115,992.77 2123.44,1001.21 2202.36,1001.21 v1(2205.7,1001.21) 2205.7,950 C44.1@2205,950
1-LDOD1: C46.1 C47.1 R70.2 R94.2 TP-VPROG1.1 U1.18 U1.46 | length 1845.4
  Top Layer w8: v1(2222,1107) v1(2222,1107) U1.18@2222.05,1054.61 ; U1.46@2575.39,1388.27 2616.11,1388.27
  Top Layer w12: C47.1@2740,1390 2740,1402.23 2777.77,1440 2910,1440 TP-VPROG1.1@2960,1490
  Top Layer w15: v1(2643.85,1058.21) 2643.85,1021.75 2695.6,970 R94.2@2738.5,970 2738.5,929.58 2766.62,901.46 2844.96,901.46 R70.2@2918.5,975
  Top Layer w16: 2616.11,1388.27 2636.56,1388.27 v1(2637,1388) 2636.56,1388.32 2636.56,1388.46 v1@2670.48,1388.46 ; v1@2676,1384.02 2671.02,1389 v1(2677,1389)
  Top Layer w24: v1@2676,1384.02 2676,1332.22 2708.22,1300 C46.1@2755,1300 ; v1(2677,1389) 2678,1390 C47.1@2740,1390
  Bottom Layer w24: v1(2222,1107) 2222,1097.03 2260.82,1058.21 v1(2643.85,1058.21) 2677,1091.36 v1(2677,1389)
1-REG50: C22.1 C23.1 C43.1 J2.2 J3.2 R77.2 R86.2 RT1.2 RT2.2 U1.32 | length 6598.8
  Top Layer w8: v1(2234.61,654.07) 2234.61,693.11 C22.1@2235,693.5 ; v1(2289,1921) 2289,1884.5 2291,1882.5 C23.1@2290,1881.5 ; U1.32@2497.64,1054.61 2497.77,1054.47 v1@2497.77,1009.77 ; C43.1@2551,935 2612.5,935 2782.5,765 R86.2@2835,765 ; R86.2@2835,768.5 R86.2@2835,765 ; R77.2@2853.5,680 2853.5,719.5 2835,738 R86.2@2835,765 ; RT2.2@4200,4440 4200,4454 4240,4494 4271,4494 J3.2@4300,4465 ; J2.2@4449.15,4465.85 4477.31,4494 4514,4494 4550,4458.01 RT1.2@4550,4440
  Top Layer w20: v1@2497.77,1009.77 v1(2497.77,999.51) 2532.49,999.51 2551,981 C43.1@2551,935
  Top Layer w24: C23.1@2290,1877 C23.1@2291.03,1877
  Bottom Layer w8: v1(2234.61,654.07) 2234.61,906.67 2327.45,999.51 v1(2497.77,999.51) 2695.51,999.51 2759,1063 2759,1758.81 2754.53,1763.28 2754.53,1856.04 ; v1(2289,1921) 2353.96,1856.04 2754.53,1856.04 ; J3.2@4300,4465 4359.43,4465 4377.62,4443.77 ; J2.2@4450,4465 4398.85,4465 4377.62,4443.77 ; 2754.53,1856.04 2855.46,1856.04 4377.62,3378.2 4377.62,4443.77
1-SCLK_N: R43.1 R103.2 U1.55 | length 892.8
  Top Layer w8: U1.55@2379.53,1508.35 2379.53,1566.62 2413.13,1600.22 v1(2413.13,1925.03) 2413.13,2031.18 2400,2044.31 R43.1@2400,2105 ; v1(2644.1,1922.03) 2685,1922.03 R103.2@2685,1920
  Bottom Layer w8: v1(2413.13,1925.03) 2482.08,1925.03 2487.11,1920 2570.01,1920 2572.04,1922.03 v1(2644.1,1922.03)
1-SCLK_S: C11.1 P8.7 R61.2 U1.26 | length 1212.6
  Top Layer w8: U1.26@2379.53,1051.65 2379.53,1006.34 2450,935.86 2450,615 v1(2555,510) ; R61.2@2555,475 v1(2555,510) ; v1(2574.05,584.02) 2625,584.02 C11.1@2625,585 ; P8.7@2595,140 2545,190 2545,300 2517.42,327.58 2517.42,492.42 2535,510 v1(2555,510)
  Bottom Layer w12: v1(2555,510) 2574.05,529.05 v1(2574.05,584.02)
1-SDI_N: R44.1 R104.2 U1.53 | length 838.6
  Top Layer w8: U1.53@2418.9,1508.35 2418.9,1545.92 2474.12,1601.14 v1(2474.12,2002.02) 2474.12,2051.57 2475,2052.45 R44.1@2475,2105 ; v1(2643.1,2002.02) 2685,2002.02 R104.2@2685,2000
  Bottom Layer w8: v1(2474.12,2002.02) 2496.58,2002.02 2503.6,1995 2570.01,1995 2577.03,2002.02 v1(2643.1,2002.02)
1-SDI_S: C12.1 P8.10 R63.2 U1.28 | length 1156.1
  Top Layer w8: U1.28@2418.9,1051.65 2418.9,1017.37 2489.82,946.45 2489.82,694.02 2523.84,660 ; C12.1@2625,660 2523.84,660 ; P8.10@2695,240 2695,295.78 2670,320.78 2670,495 2685,510 v1(2705,510) ; R63.2@2705,475 v1(2705,510) ; 2523.84,660 2523.84,600.29 2575.13,549 2666,549 v1(2705,510)
1-SDO_N: C35.1 R41.1 U1.54 | length 1165
  Top Layer w8: U1.54@2399.21,1508.35 2399.21,1550.84 2441.12,1592.75 v1(2441.12,1750.04) 2441.12,2344.65 2530,2433.53 R41.1@2530,2485 ; v1(2538.46,1749.78) 2575,1749.78 C35.1@2575,1750
  Bottom Layer w8: v1(2441.12,1750.04) 2489.66,1750.04 2489.92,1749.78 v1(2538.46,1749.78)
1-SDO_S: R62.2 R65.2 U1.27 | length 1017.8
  Top Layer w8: U1.27@2399.21,1051.65 2399.21,1012.36 2470,941.57 2470,631.5 2591.5,510 v1(2630,510) R62.2@2630,475
  Top Layer w12: v1(2878,578) 2879,577 R65.2@2879,531.57
  Bottom Layer w12: v1(2630,510) 2660,540 2840,540 v1(2878,578)
1-SPI-MISO: P7.5 R206.2 U1.41 | length 1536.5
  Top Layer w8: U1.41@2578.35,1289.84 2656.17,1289.84 2700.01,1246 2966,1246 3012.19,1292.19 3012.19,1471.41 3030.42,1489.64 v1(3030.42,1526.65) ; P7.5@3180,1550 3230,1600 3309,1600 3332.47,1623.47 3332.47,1852.47 3380,1900 R206.2@3565,1900
  Bottom Layer w8: v1(3030.42,1526.65) 3083.29,1526.65 3106.64,1550 P7.5@3180,1550
1-SPI-MOSI: P7.8 R82.1 R201.2 U1.42 | length 1932.5
  Top Layer w8: U1.42@2578.35,1309.53 2661.93,1309.53 2701.46,1270 v1(2910.15,1270) ; R82.1@3265,1095 3270,1100 3270,1155.03 3135.5,1289.53 3135.5,1368.43 3167.07,1400 3200.15,1400 3218.83,1418.68 3248.68,1418.68 P7.8@3280,1450 3370,1540 3370,1730 3390,1750 R201.2@3565,1750
  Bottom Layer w8: v1(2910.15,1270) 2950,1270 3010.97,1330.97 3010.97,1455.6 3049.87,1494.5 3235.5,1494.5 P7.8@3280,1450
1-SPI-SCLK: P7.7 R80.1 R203.2 U1.40 | length 1923.9
  Top Layer w8: U1.40@2578.35,1270.16 2651.01,1270.16 2691.17,1230 2980,1230 3035,1285 3035,1445.69 v1(3036.44,1447.13) ; R80.1@3195,1095 3167,1095 3119.5,1142.5 3119.5,1376.02 3141.15,1397.67 3141.15,1411.15 P7.7@3180,1450 3230,1500 3305,1500 3349.97,1544.97 3349.97,1804.97 3370,1825 R203.2@3565,1825
  Bottom Layer w8: v1(3036.44,1447.13) 3083.29,1447.13 3086.16,1450 P7.7@3180,1450
1-SPI-SS: P7.9 R73.1 R197.2 | length 954.2
  Top Layer w8: R73.1@3335,1095 3335,1195 P7.9@3180,1350 3230,1400 3318,1400 3386,1468 3386,1665 3396,1675 R197.2@3565,1675
1-VBAT: C16.1 C35.2 C36.2 C37.2 C38.2 C41.1 R46.1 R68.2 U1.63 U1.64 Z1.2 | length 2336.9
  Top Layer w8: U1.64@2202.36,1508.35 2201.91,1508.8 v1(2201.91,1564.12) 2222.05,1543.98 U1.63@2222.05,1508.35 ; v1(2569.42,1572.72) 2598.46,1572.72 2645,1619.26 2645,1670 2673.68,1670 2693.45,1689.78 2693.45,1749.78 2693,1750.23 ; C35.2@2645,1750 2645,1750.23 2693,1750.23 ; C37.2@2645,1830 2676.41,1830 2693,1813.41 2693,1750.23
  Top Layer w12: 1985,2142.55 C38.2@2060.67,2142.55 ; R46.1@1985,2217.91 1985,1732.34 2008.94,1708.4 2008.94,1611.69
  Top Layer w24: Z1.2@1820,1750.5 1820,1692.33 1836.19,1676.14 1930,1676.14 ; R68.2@1930,1755 1930,1676.14 ; C16.1@2060,1685 2060,1611.69 ; C41.1@2180,1635 2180,1585.32 ; v1(2201.91,1564.12) 2201.55,1563.77 2180,1585.32 ; 1930,1676.14 1930,1653.87 1972.18,1611.69 2008.94,1611.69 2060,1611.69 ; 2060,1611.69 2089,1611.69 2122.69,1578 2180,1578 2180,1585.32
  Bottom Layer w8: v1(2201.91,1564.12) 2347.11,1564.12 2362.99,1580 2537,1580 2544.28,1572.72 v1(2569.42,1572.72)
1-VC0: C8.1 C9.2 C10.2 C11.2 C12.2 C13.2 C14.2 C16.2 C18.2 C21.2 C26.2 C29.2 C31.2 C32.2 C39.2 C40.2 C41.2 C42.2 C43.2 C44.2 C45.2 C46.2 C47.2 C120.2 C123.2 C130.2 C131.2 C132.2 C135.2 C137.2 D5.2 D6.2 JP18.1 P1.7 P7.2 P7.10 P8.5 P8.6 Q2.4 Q2.7 Q5.4 Q5.7 Q8.4 Q8.7 R53.1 R53.2 R57.1 R58.1 R59.1 R60.1 R61.1 R62.1 R63.1 R64.1 R75.1 R80.2 R82.2 R83.2 R96.1 R101.2 R103.1 R104.1 R105.1 R108.2 R112.1 R202.1 R213.1 TP6.1 TP-VSS1.1 TP-VSS3.1 U1.13 U1.14 U1.15 U1.25 U1.33 U1.34 U1.35 U1.49 U1.50 U1.65 U4.2 U4.8 U6.9 U6.15 U9.2 U9.3 Z1.1 Z12.2 Z13.2 | length 5491.2
  Top Layer w8: v1(1890.07,626.39) 1926,626.39 C10.2@1926,626 ; U1.15@2124.61,1152.05 2071.95,1152.05 v1(2066,1158) 2079.73,1171.73 U1.14@2124.61,1171.73 ; v1(2254.61,370.07) R57.1@2254.61,406 ; v1(2329.61,370.07) R58.1@2329.61,406 ; v1(2406.61,369.07) R59.1@2406.61,405 ; U1.50@2477.95,1505.39 2477.95,1545.95 2488,1556 v1(2513,1556) 2497.64,1540.64 U1.49@2497.64,1505.39 ; v1(2480.61,369.07) R60.1@2480.61,405 ; v1(2554.61,369.07) R61.1@2554.61,405 ; U1.33@2575.39,1132.36 v1@2624.64,1132.36 ; U1.34@2575.39,1152.05 2623.95,1152.05 2624.64,1151.36 ; U1.35@2575.39,1171.73 2614.27,1171.73 2626,1160 v1(2626,1131) ; v1(2630.61,369.07) R62.1@2630.61,405 ; v1(2704.61,368.07) R63.1@2704.61,404 ; v1(2779.61,368.07) R64.1@2779.61,404 ; R83.2@3190,2090 v1(3190,2132.48) ; v1(3194.93,986.71) 3194.93,1025 R80.2@3195,1025 ; v1(3269.93,986.71) 3269.93,1025 R82.2@3270,1025
  Top Layer w10: U1.25@2359.84,1054.61 2359.84,1108.84 v1(2360,1109)
  Top Layer w12: v1(3714.8,1625.2) 3714.9,1625.1 U6.15@3785.4,1625.1 ; v1(3714.8,1925.2) 3714.9,1925.1 U6.9@3785.4,1925.1 ; v1(3865,2050) 3865.1,2049.9 U4.8@3935.6,2049.9
  Top Layer w20: v1(1658,1350) C21.2@1700.5,1350 ; v1(1658,1429) C18.2@1700.5,1429 ; v1(1658,1510) C14.2@1700.5,1510 ; v1(1659,1191) C29.2@1701.5,1191 ; v1(1659,1269) C26.2@1701.5,1269 ; v1(1799.52,1030) 1845.5,1030 ; v1(1802.52,1110) C40.2@1848.5,1110 ; Z1.1@1820,1898.74 v1(1820,1964) v1(1820,1996) ; C39.2@2003,842.57 C39.2@2005,844.57 ; C16.2@2060,1751.5 v1(2060,1797) ; C41.2@2180,1704.43 v1(2180,1757) ; v1(2208,835) C44.2@2208,883.5 ; v1(2697,1049) 2737.5,1049 R96.1@2738.5,1050 ; C46.2@2821.5,1308 2823.5,1310 v1(2870,1310) ; R75.1@3256.5,940 v1(3309,940) ; C120.2@3475,2156.5 v1(3475,2202) ; R202.1@3518.5,2250 3521,2252.5 v1(3521,2291) ; C130.2@3526,1056.5 3527,1057.5 v1(3527,1108) ; v1(3570,1575) C123.2@3618.5,1575 ; C132.2@3650,830.5 3651,831.5 v1(3651,886) ; C131.2@3750,831.5 3751,832.5 v1(3751,886) ; R213.1@3775,1018.5 3776,1017.5 v1(3776,965)
  Top Layer w24: v1(733,2187) 733,2222 ; C45.2@2115,850 2115.21,850 v1(2115.21,790.72) ; v1(2552,764) v1(2552,807) C43.2@2552,858 ; C11.2@2686.31,585.97 v1(2734.74,585.97) ; C12.2@2687.31,659.97 v1(2735.74,659.97) ; C13.2@2688.31,736.97 v1(2736.74,736.97) ; R105.1@2758,2081 2758,2079.97 v1(2806.43,2079.97) ; R103.1@2759,1923.2 2759,1922.17 v1(2807.43,1922.17) ; R104.1@2760,2000 2760,1998.97 v1(2808.43,1998.97) ; C47.2@2820,1390 2820,1389.76 v1(2866.76,1389.76) v1@2866.76,1390.04 ; R108.2@2842,1557 2842,1555.97 2851.03,1565 v1(2895,1565) ; R101.2@2842,1632 2842,1630.97 v1(2890.43,1630.97) ; C31.2@2843,1482 2843,1480.97 v1(2891.43,1480.97) ; C32.2@2844,1707 2844,1705.97 v1(2892.43,1705.97) ; v1@3135,2203 C9.2@3135.04,2243 ; v1(3590,345) D5.2@3642.5,345 ; v1(3595,550) D6.2@3642.5,550 ; U9.2@3650,1005 3650,960 v1(3670,940) 3685,955 3687,955 U9.3@3687,1005 ; v1(3685,2400) C135.2@3735,2400 ; v1(3860,2350) 3860.1,2349.9 U4.2@3935.6,2349.9 ; v1(3939.3,119.12) 3983.5,119.12 3983.5,179.39 3940.07,179.39 v1(3940.07,179.64)
  Top Layer w48: P1.7@200,1038.22 250.23,988 456,988 456,896.75 450,890.75 450,790
  Bottom Layer w48: JP18.1@456,990 456,904.32 570,790.32 570,315 785,100 v1(939,100) v1(980,100) ; v1(1490,89) 1490,219 1515,244 v1(1515,373)
  other v1: 400,100 600,100 1850,100 2050,100 2900,100 3100,100 3300,100 896,101 1489.84,132.25 3350,250 1515.19,329.82 1650,350 100,450 3350,450 100,650 1650,700 3010,780 311,791 351,791 2002.52,793 310,832 351,832 100,850 1650,1000 100,1050 3140,1050 100,1250 100,1450 100,1650 1650,1800 100,1850 1717,1996 100,2050 3280.82,2111.15 3135,2204
  other v2: 2247.64,1177.64 2298.82,1177.64 2350,1177.64 2401.18,1177.64 2452.36,1177.64 2247.64,1228.82 2298.82,1228.82 2350,1228.82 2401.18,1228.82 2452.36,1228.82 2247.64,1280 2298.82,1280 2350,1280 2401.18,1280 2452.36,1280 2247.64,1331.18 2298.82,1331.18 2350,1331.18 2401.18,1331.18 2452.36,1331.18 2247.64,1382.36 2298.82,1382.36 2350,1382.36 2401.18,1382.36 2452.36,1382.36
1-VC1: C30.2 C40.1 R109.1 U1.11 | length 1154.7
  Top Layer w8: R109.1@1601.5,500 1640,500 1752.42,612.42 1752.42,1032.82 1786.08,1066.48 1899.48,1066.48 1911.5,1078.5 C40.1@1911.5,1110 1912.45,1110 1952,1149.55 1952,1190 ; C30.2@1911.5,1190 1952,1190 ; U1.11@2124.61,1230.79 2014.95,1230.79 1974.17,1190 1952,1190
1-VC2: C27.2 C29.1 C30.1 R98.1 U1.9 | length 1153.1
  Top Layer w8: R98.1@1605,850 1673.26,850 1708.43,885.17 1708.43,1016.24 1633.31,1091.35 1633.31,1199.94 1663.2,1229.83 1807.29,1229.83 1938.06,1229.83 1952.12,1243.89 1952.12,1270.33 ; C29.1@1765,1190 1806.73,1190 ; 1806.73,1229.27 1806.73,1190 ; C30.1@1845,1190 1806.73,1190 ; C27.2@1915,1270.33 1952.12,1270.33 ; 2028.96,1270.33 1952.12,1270.33 ; 2029.13,1270.16 U1.9@2121.65,1270.16
1-VC3: C24.2 C26.1 C27.1 R92.1 U1.7 | length 803.3
  Top Layer w8: R92.1@1605,1200 1605,1206 1635,1236 1635,1284.94 1660.32,1310.26 1805.89,1310.26 1942.28,1310.26 1952.12,1320.1 1952.12,1349.35 ; C26.1@1765,1270 1804.48,1270 ; 1804.48,1308.86 1804.48,1270 ; C27.1@1845,1270 1804.48,1270 ; C24.2@1915,1349.35 1952.12,1349.35 ; U1.7@2124.61,1309.53 2022.96,1309.53 1983.13,1349.35 1952.12,1349.35
1-VC4: C19.2 C21.1 C24.1 R79.1 U1.5 | length 867.5
  Top Layer w8: R79.1@1605,1550 1605,1443.57 1646.13,1402.45 1658.17,1390.41 1941.44,1390.41 1953.53,1402.5 1953.53,1428.94 ; C21.1@1765,1350 1804.76,1350 ; 1804.76,1389.29 1804.76,1350 ; C24.1@1845,1350 1804.76,1350 ; C19.2@1915,1428.94 1953.53,1428.94 ; U1.5@2121.65,1348.9 2052.1,1348.9 1972.06,1428.94 1953.53,1428.94
1-VC5: C15.2 C18.1 C19.1 R72.1 U1.3 | length 1272.6
  Top Layer w8: R72.1@1605,1925 1655.83,1925 1698.46,1882.36 1698.46,1590.46 1633,1524.99 1633,1496.01 1652.11,1476.89 1658.99,1470 1806,1470 ; C18.1@1765,1430 1805.32,1430 ; 1805.32,1468.59 1805.32,1430 ; 1806.45,1469.72 1942.28,1469.72 1949.59,1477.03 1949.59,1509.65 ; C19.1@1845,1430 1805.32,1430 ; C15.2@1915,1509.65 1949.59,1509.65 ; U1.3@2121.65,1388.27 2074.73,1388.27 2016,1447 2016,1463.87 1970.22,1509.65 1949.59,1509.65
1-VC6: C14.1 C15.1 R67.1 U1.1 | length 1082.2
  Top Layer w8: 1805.83,1575.17 2019.05,1575.17 2061,1533.22 2061,1451 2084.36,1427.64 U1.1@2124.61,1427.64
  Top Layer w12: R67.1@1755.02,2056.45 1755.02,1664.98 1805,1615 1805,1510 ; C14.1@1761.5,1510 1805,1510 ; C15.1@1848.5,1510 1805,1510
2-ALERT_N: C63.2 R21.1 U2.57 | length 1355.8
  Top Layer w8: U2.57@2340.16,3678.35 2340.16,3883.21 2363.89,3906.95 2363.89,4075.31 2390.49,4101.9 v1(2390.49,4175.18) 2390.49,4208.36 2390.82,4208.69 2390.82,4291.5 2384.57,4297.75 2384.57,4600 2420,4635.43 R21.1@2420,4745 ; v1(2579.03,4176.02) 2635,4176.02 C63.2@2635,4170
  Bottom Layer w8: v1(2390.49,4175.18) 2484.34,4175.18 2485.18,4176.02 v1(2579.03,4176.02)
2-ALERT_S: R39.2 U2.23 | length 715.7
  Top Layer w8: U2.23@2320.47,3221.65 2320.47,3172.06 2394.5,3098.03 2394.5,2685.86 2350,2641.36 R39.2@2350,2555
2-CB1: R148.1 U2.12 | length 1214.8
  Top Layer w8: R148.1@1601.5,2475 1605.5,2479 v1(1650,2479) ; v1(1975,3344) 2012.1,3381.1 U2.12@2124.61,3381.1
  Bottom Layer w8: v1(1650,2479) 1975,2804 v1(1975,3344)
2-CB2: R142.1 U2.10 | length 947.2
  Top Layer w8: R142.1@1601.5,2875 v1(1656.58,2875.02) ; v1(1975,3424.11) 2003.89,3424.11 2007.53,3420.47 U2.10@2124.61,3420.47
  Bottom Layer w8: v1(1656.58,2875.02) 1743.1,2875.02 1873.88,3005.8 1873.88,3338.88 1959.11,3424.11 v1(1975,3424.11)
2-CB3: R136.1 U2.8 | length 624.7
  Top Layer w8: R136.1@1603.5,3252 v1(1650,3252) ; v1(2017.69,3481.01) 2038.86,3459.84 U2.8@2124.61,3459.84
  Bottom Layer w8: v1(1650,3252) 1879.01,3481.01 v1(2017.69,3481.01)
2-CB4: R125.1 U2.6 | length 559.5
  Top Layer w8: R125.1@1596.5,3575 1603.5,3568 v1(1640,3568) ; v1(1974,3560.02) 1988.02,3546 2011.43,3546 2058.21,3499.21 U2.6@2124.61,3499.21
  Bottom Layer w8: v1(1640,3568) 1707,3568 1714.98,3560.02 v1(1974,3560.02)
2-CB5: R120.1 U2.4 | length 736.2
  Top Layer w8: R120.1@1601.5,3950 1603.5,3952 v1(1647,3952) ; v1(1999,3608) 1999,3605 2065.42,3538.58 U2.4@2124.61,3538.58
  Bottom Layer w8: v1(1647,3952) 1647,3885 1924,3608 v1(1999,3608)
2-CB6: R116.1 U2.2 | length 971.8
  Top Layer w8: R116.1@1603.5,4277 v1(1654,4277) ; v1(2037,3659) 2039.94,3656.06 2039.94,3616.06 2078.05,3577.95 U2.2@2124.61,3577.95
  Bottom Layer w8: v1(1654,4277) 1688.58,4242.42 1688.58,4022.97 2037,3674.55 v1(2037,3659)
2-CELL1: C69.2 C80.1 JP11.1 P2.6 Q14.4 Q14.7 R35.2 R143.1 R145.2 R147.2 Z23.2 Z24.2 Z25.1 | length 2630.3
  Top Layer w24: JP11.1@456,3254 456,3200.35 480.05,3176.3 823.52,3176.3 838.27,3161.55 838.27,3124.89 818.38,3105 R35.2@770,3105 ; R147.2@995,2640 995,2545 1005,2535 1236.45,2535 1252.13,2519.32 1252.13,2485 1235.22,2468.09 1189.5,2468.09 Z25.1@1189.5,2480
  Bottom Layer w48: P2.6@200,3211.02 310.41,3211.02 353.39,3254 456,3254 522,3320 577.68,3320 721,3176.68 721,2815 781,2755 v1(905,2755) v1(960,2755) v1(1010,2755) ; v1(1485,2776) 1485,2903 1520,2938 v1(1520,3007) v1(1520,3047)
  other v1: 1484.32,2818.49
2-CELL2: C66.2 C69.1 JP10.1 P2.5 Q13.4 Q13.7 R34.2 R137.1 R138.2 R139.2 Z21.2 Z22.2 Z23.1 | length 2382.8
  Top Layer w24: JP10.1@456,3404 456,3350.35 480.05,3326.3 823.52,3326.3 838.27,3311.55 838.27,3274.89 818.38,3255 R34.2@770,3255 ; R139.2@995,2990 995,2900 1010,2885 1236.45,2885 1254.14,2867.31 1254.14,2846.14 1238,2830 Z23.1@1189.5,2830
  Bottom Layer w48: P2.5@200,3348.82 304.31,3348.82 359.49,3404 456,3404 522,3470 577.68,3470 777,3270.68 777,3150 812,3115 v1(905,3115) v1(955,3115) v1(1000,3115) ; v1(1485,3143) 1485,3297 1520,3332 v1(1520,3383) v1(1520,3423)
  other v1: 1484,3183
2-CELL3: C57.2 C66.1 JP9.1 P2.4 Q11.4 Q11.7 R33.2 R129.1 R131.2 R133.2 Z19.2 Z20.2 Z21.1 | length 2247.4
  Top Layer w24: JP9.1@456,3554 456,3500.35 480.05,3476.3 823.52,3476.3 838.27,3461.55 838.27,3424.89 818.38,3405 R33.2@770,3405 ; R133.2@995,3340 995,3255 1005,3245 1226.45,3245 1250.13,3221.32 1250.13,3202.07 1235.3,3187.24 1189.5,3187.24 Z21.1@1189.5,3180
  Bottom Layer w48: P2.4@200,3486.61 267.39,3554 456,3554 522,3620 580,3620 730,3470 v1(915,3470) v1(970,3470) v1(1020,3470) ; v1(1485,3487) 1485,3623 1520,3658 v1(1520,3770)
  other v1: 1484.44,3528.57 1519,3730
2-CELL4: C54.2 C57.1 JP8.1 P2.3 Q10.4 Q10.7 R32.2 R121.1 R122.2 R124.2 Z17.2 Z18.2 Z19.1 | length 2194.7
  Top Layer w24: JP8.1@456,3704 456,3650.35 480.05,3626.3 823.52,3626.3 838.27,3611.55 838.27,3574.89 818.38,3555 R32.2@770,3555 ; R124.2@997,3689 997,3607 1009,3595 1226.45,3595 1250.13,3571.32 1250.13,3554.31 1234.95,3539.13 1198.63,3539.13 Z19.1@1189.5,3530
  Bottom Layer w48: P2.3@200,3624.41 279.59,3704 456,3704 537,3785 735,3785 765,3815 v1(900,3815) v1(955,3815) v1(1010,3815) ; v1(1485,3832) 1485,4014 1520,4049 v1(1520,4079) 1520,4119 v1(1520.19,4120.49)
  other v1: 1484.8,3873.93
2-CELL5: C51.2 C54.1 JP7.1 P2.2 Q9.4 Q9.7 R31.2 R117.1 R118.2 R119.2 Z14.2 Z16.2 Z17.1 | length 2284.5
  Top Layer w24: JP7.1@456,3854 456,3800.35 480.05,3776.3 823.52,3776.3 838.27,3761.55 838.27,3724.89 818.38,3705 R31.2@770,3705 ; R119.2@995,4040 995,3950 1005,3940 1231.45,3940 1258.14,3913.31 1258.14,3893.51 1244.63,3880 Z17.1@1189.5,3880
  Bottom Layer w48: P2.2@200,3762.2 291.8,3854 456,3854 531,3929 568.68,3929 662,4022.32 662,4024.23 740.77,4103 781,4103 842,4164 905,4164 v1(905,4165) v1(960,4165) v1(1025,4165) ; v1(1490,4188) v1(1490,4228) 1490,4299 1515,4324 v1(1515,4396) 1515,4436 v1(1514.43,4441.04)
2-CELL6: C51.1 J4.1 P2.1 R20.1 R30.2 R113.2 R114.2 TP3.1 TP-C3.1 Z14.1 | length 3710.3
  Top Layer w12: R113.2@995,4390 995,4465 1010,4480 1595,4480 TP-C3.1@1640,4435 1640,4385 1665,4360 R114.2@1665,4330
  Top Layer w20: 200,4495 R20.1@200,4520
  Top Layer w24: P2.1@200,3900 295,3900 369.9,3974.9 369.9,4035.9 409,4075 J4.1@455,4075 ; TP3.1@510,4235 510,4142.75 456,4088.75 456,3950.35 480.05,3926.3 823.52,3926.3 838.27,3911.55 838.27,3874.89 818.38,3855 R30.2@770,3855 ; R113.2@995,4390 995,4305 1010,4290 1231.45,4290 1248.03,4273.42 1248.03,4244.55 1236.11,4232.63 1189.5,4232.63 Z14.1@1189.5,4230
  Top Layer w48: P2.1@200,3900 200,4495
  Bottom Layer w48: J4.1@455,4075 795,4415 v1(876,4415) 915,4415 v1(916,4414)
2-CONV_N: R25.1 U2.59 | length 632.9
  Top Layer w8: R25.1@2300,4295 2300,4188.07 2320,4168.07 2320,3943.56 2300.79,3924.34 U2.59@2300.79,3678.35
2-CONV_S: C76.1 R42.2 U2.21 | length 1226.2
  Top Layer w8: C76.1@2165,2650 2206.01,2650 ; R42.2@2270,2175 2270,2332.79 2207.61,2395.18 2207.61,2648.4 2206.01,2650 ; U2.21@2281.1,3221.65 2281.1,3166.17 2362.5,3084.78 2362.5,2783.47 2229.03,2650 2206.01,2650
2-CS_N: R28.1 U2.52 | length 692.7
  Top Layer w8: U2.52@2438.58,3678.35 2438.58,3783.58 2548.01,3893.01 2548.01,4233.01 2610,4295 R28.1@2615,4295
2-CS_S: C75.1 R45.2 U2.29 | length 1202.2
  Top Layer w8: U2.29@2438.58,3221.65 2438.58,3184.92 2507.93,3115.57 2507.93,2972.61 2587.41,2893.13 2587.41,2611.96 ; R45.2@2550,2175 2550,2288.83 2587.41,2326.24 2587.41,2611.96 ; C75.1@2665,2610 2621.69,2610 2619.72,2611.96 2587.41,2611.96
2-DRDY_N: C62.2 R24.1 U2.58 | length 1263
  Top Layer w8: U2.58@2320.47,3678.35 2320.47,3889.1 2341.84,3910.47 2341.84,4173.66 2366.82,4198.63 v1(2366.82,4231.82) 2366.82,4338.54 2354.98,4350.38 2354.98,4449.1 2330,4474.09 R24.1@2330,4745
  Top Layer w12: C62.2@2215,4220 2215,4226.86 2265.37,4226.86 2266.72,4225.51 v1(2266.91,4225.51)
  Bottom Layer w8: v1(2266.91,4225.51) 2310.2,4225.51 2315.67,4230.98 2316.52,4231.82 v1(2366.82,4231.82)
2-DRDY_S: R38.2 U2.22 | length 747.9
  Top Layer w8: R38.2@2260,2555 2260,2609.91 2378.5,2728.41 2378.5,3091.4 2300.79,3169.11 U2.22@2300.79,3221.65
2-FAULT_N: C64.2 R22.1 U2.56 | length 1360.9
  Top Layer w8: U2.56@2359.84,3675.39 2359.84,3877.33 2385.95,3903.43 2385.95,4021.46 2415.49,4051 v1(2415.49,4092.35) 2415.49,4227.02 2409,4233.51 2409,4589 2510,4690 R22.1@2510,4745 ; v1(2584.47,4093.69) 2635,4093.69 C64.2@2635,4090
  Bottom Layer w8: v1(2415.49,4092.35) 2483.85,4092.35 2485.18,4093.69 v1(2584.47,4093.69)
2-FAULT_S: R40.2 U2.24 | length 711
  Top Layer w8: U2.24@2340.16,3224.61 2340.16,3184.48 2440,3084.64 R40.2@2440,2555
